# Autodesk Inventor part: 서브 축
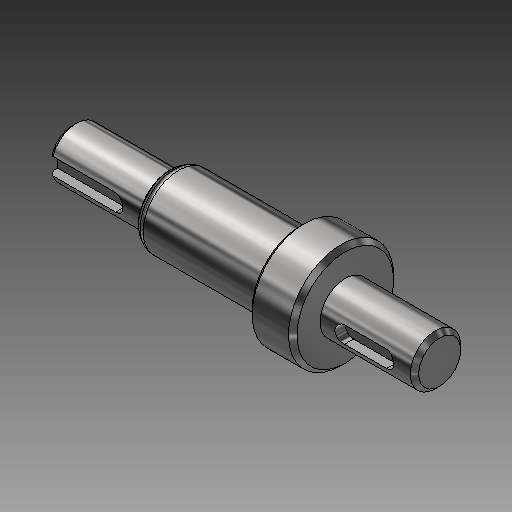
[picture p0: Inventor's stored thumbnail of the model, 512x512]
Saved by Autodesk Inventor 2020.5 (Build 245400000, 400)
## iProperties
Created: 2016-04
Part Number: 서브 축
Document SubType Name: Modeling
Designer: mdu
Density: 1 g/cm^3
Mass: 19.9624 g
Surface Area: 57.7178 cm^2
Volume: 19.9624 cm^3
Material: 강철, 연강
Appearance: 반광택
Author: mdu
Revision Number: 1
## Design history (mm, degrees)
sketch "스케치1"
  geometry: L1 (-16.331, 0)-(-103.831, 0); L2 (-16.331, 0)-(-16.331, -6); L3 (-16.331, -6)-(-38.831, -6); L4 (-38.831, -12.5)-(-46.5, -12.5); L5 (-46.5, -8.5)-(-79.013, -8.5); L6 (-103.831, -6)-(-103.831, 0); L7 (-46.5, -8.5)-(-46.5, -12.5); L8 (-38.831, -6)-(-38.831, -12.5); L9 (-46.5, 12.249)-(-46.5, -12.249) reference; L10 (-38.831, -17)-(-38.831, 17) reference; L11 (-103.831, -6)-(-80.831, -6); L12 (-80.831, -6)-(-80.831, -7.45); L13 (-80.831, -7.45)-(-79.013, -8.5); 2 further points
  constraints: 23 end point, 6 perpendicular, 2 collinear, 2 parallel, 1 horizontal, 1 midpoint, 1 point on line
  dimensions: "d1" = 12 diameter of L3 L1; "d2" = 25 diameter of L4 L1; "d3" = 17 diameter of L5 L1; "d18" = 22.5 distance of L2.end L3.end; "d20" = 65 distance between parallel lines of L6 L8; "d21" = 7.66872 distance of L4.start L4.end (derived); "d28" = 12 diameter of L11 L1; "d29" = 23 distance of L6.start L11.end; "d30" = 14.9 diameter of L12.end L1; "d32" = 30 deg angle of L5 L13
revolve "회전1" sketch "스케치1" stored, may be unused: angle "d5" = 90 deg
chamfer "모따기1" distance "d6" = 1; stored, may be unused: second distance "d7" = 2, angle "d8" = 45 deg
node "작업 평면1"
sketch "스케치2"
  geometry: L1 (11.25, 5)-(11.25, -5) reference; L2 (-5.75, -2)-(4.25, -2); L3 (4.25, 2)-(-5.75, 2); A1 r 2 centre (4.25, 0) between (4.25, -2) and (4.25, 2); A2 r 2 centre (-5.75, 0) between (-5.75, 2) and (-5.75, -2); 2 further points
  constraints: 4 end point, 4 point on circle, 4 tangent, 2 centre point, 1 horizontal alignment, 1 midpoint, 1 parallel, 1 perpendicular
  dimensions: "d9" = 4 distance between parallel lines of L2 L3; "d10" = 14 dimension on A1 A2; "d11" = 5 distance edge to line of A1 L1
extrude "돌출1" cut sketch "스케치2" distance "d12" = 2.5; taper "d13" = 0 deg
node "작업 평면2"
sketch "스케치3"
  geometry: L1 (-103.831, -5)-(-103.831, 5) reference; L2 (-103.831, 2)-(-87.831, 2); L3 (-87.831, -2)-(-103.831, -2); A1 r 2 centre (-87.831, 0) between (-87.831, -2) and (-87.831, 2); 2 further points
  constraints: 4 end point, 2 perpendicular, 2 point on circle, 2 point on line, 2 tangent, 1 centre point, 1 horizontal alignment, 1 midpoint
  dimensions: "d14" = 4 distance between parallel lines of L3 L2; "d15" = 18 dimension on A1 L1
extrude "돌출2" cut sketch "스케치3" distance "d16" = 2.5; taper "d17" = 0 deg
sketch "스케치4"
  geometry: C1 r 12.5 at (0, 0) reference; 1 further point
extrude "돌출3" join sketch "스케치4" distance "d22" = 3; taper "d23" = 0 deg
chamfer "모따기2" distance "d24" = 1; stored, may be unused: second distance "d25" = 2, angle "d26" = 45 deg
fillet "모깎기1" dims "d34" = 1
fillet "모깎기2" dims "d35" = 2
node "솔리드1"
node "참조4"
node "참조5"
other parameters: "d33" = 6
